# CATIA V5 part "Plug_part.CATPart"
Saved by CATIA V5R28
Part number: Plug_part
Definition: design
Nomenclature: Plug_part
Source: Unknown
Bounding box of the stored display mesh (mm): x -6.965 to 6.965, y -6.945 to 6.945, z 13.901 to 26.702
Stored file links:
  D:\paraturbo-cad\STEP\Turbocompressor_for_Christophe\Plug_part.CATPart
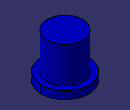
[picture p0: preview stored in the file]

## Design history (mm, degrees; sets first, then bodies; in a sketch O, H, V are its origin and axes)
Body1 "MANIFOLD_SOLID_BREP #711" (main body)
  Solid1: solid without history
